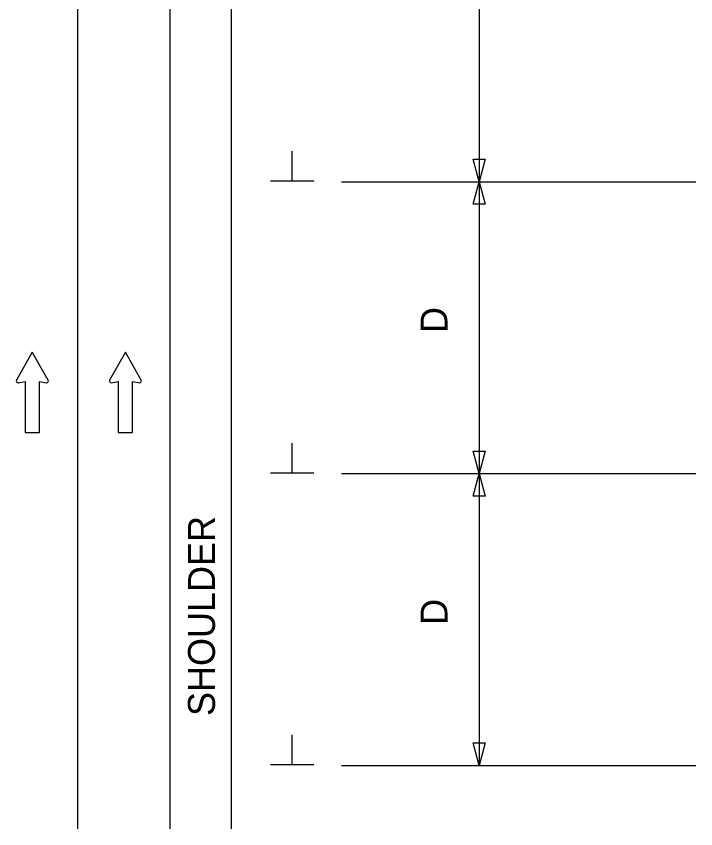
# Model space of a CAD drawing. Extents: x 19023 to 20762, y 4888 to 6104.
# Drawn here: x 19347 to 19523.7, y 5261 to 5472.4 of the extents above; entities that cross this region are included whole.
import ezdxf

# ---------------------------------------------------------------- set-up
doc = ezdxf.new("R2010")
doc.units = 0
for name, color, linetype in [('MT_SCRATCH_LEVEL_E', 7, 'Continuous'), ('PAVT_EDGE_EX', 7, 'Continuous'), ('TYPICAL_TEXT_DIMEN_PR', 7, 'Continuous')]:
    doc.layers.add(name, color=color, linetype=linetype)

msp = doc.modelspace()

# ---------------------------------------------------------------- linework, layer by layer
at = {"layer": 'MT_SCRATCH_LEVEL_E'}
for p, q in [((19351.148, 5384.986), (19347.037, 5377.745)), ((19351.148, 5384.986), (19347.037, 5377.745)), ((19355.295, 5377.745), (19351.148, 5384.986)), ((19355.295, 5377.745), (19351.148, 5384.986)), ((19375.362, 5384.986), (19371.251, 5377.745)), ((19375.362, 5384.986), (19371.251, 5377.745)), ((19379.509, 5377.745), (19375.362, 5384.986)), ((19379.509, 5377.745), (19375.362, 5384.986)), ((19347.519, 5377.061), (19349.296, 5377.377)), ((19347.519, 5377.061), (19349.296, 5377.377)), ((19349.296, 5377.377), (19349.296, 5364.119)), ((19349.296, 5377.377), (19349.296, 5364.119)), ((19353.038, 5364.119), (19353.038, 5377.377)), ((19353.038, 5377.377), (19354.816, 5377.061)), ((19353.038, 5364.119), (19353.038, 5377.377)), ((19353.038, 5377.377), (19354.816, 5377.061)), ((19371.733, 5377.061), (19373.51, 5377.377)), ((19371.733, 5377.061), (19373.51, 5377.377)), ((19373.51, 5377.377), (19373.51, 5364.119)), ((19373.51, 5377.377), (19373.51, 5364.119)), ((19377.252, 5364.119), (19377.252, 5377.377)), ((19377.252, 5377.377), (19379.03, 5377.061)), ((19377.252, 5364.119), (19377.252, 5377.377)), ((19377.252, 5377.377), (19379.03, 5377.061)), ((19349.296, 5364.119), (19353.038, 5364.119)), ((19349.296, 5364.119), (19353.038, 5364.119)), ((19373.51, 5364.119), (19377.252, 5364.119)), ((19373.51, 5364.119), (19377.252, 5364.119))]:
    msp.add_line(p, q, dxfattribs=at)
for centre, start, end in [((19347.445, 5377.521), 150.42484, 279.96381), ((19347.445, 5377.521), 150.42484, 279.96381), ((19354.885, 5377.522), 260.03619, 29.77312), ((19354.885, 5377.522), 260.03619, 29.77312), ((19371.659, 5377.521), 150.42484, 279.96381), ((19371.659, 5377.521), 150.42484, 279.96381), ((19379.099, 5377.522), 260.03619, 29.77312), ((19379.099, 5377.522), 260.03619, 29.77312)]:
    msp.add_arc(centre, 0.463, start, end, dxfattribs=at)
at = {"layer": 'PAVT_EDGE_EX'}
for p, q in [((19386.917, 6104.026), (19386.917, 5261.047)), ((19402.917, 6104.026), (19402.917, 5261.047)), ((19362.917, 6014.455), (19362.917, 5261.047))]:
    msp.add_line(p, q, dxfattribs=at)
for points in [[(19362.917, 5414.455), (19362.917, 5389.455)], [(19362.917, 5314.455), (19362.917, 5289.455)]]:
    msp.add_lwpolyline(points, dxfattribs=at)
at = {"layer": 'TYPICAL_TEXT_DIMEN_PR'}
for p, q in [((19467.405, 5581.162), (19467.405, 5277.497)), ((19418.735, 5429.493), (19418.735, 5437.278)), ((19418.761, 5429.493), (19418.761, 5437.278)), ((19418.761, 5429.493), (19418.761, 5437.278)), ((19467.389, 5429.339), (19465.818, 5435.201)), ((19465.818, 5435.201), (19467.389, 5435.201)), ((19467.389, 5435.201), (19468.96, 5435.201)), ((19468.96, 5435.201), (19467.389, 5429.339)), ((19418.735, 5429.493), (19413.11, 5429.493)), ((19418.761, 5429.493), (19413.136, 5429.493)), ((19418.761, 5429.493), (19413.136, 5429.493)), ((19424.36, 5429.493), (19418.735, 5429.493)), ((19424.386, 5429.493), (19418.761, 5429.493)), ((19424.386, 5429.493), (19418.761, 5429.493)), ((19431.588, 5429.331), (19523.722, 5429.331)), ((19465.815, 5423.484), (19467.386, 5429.346)), ((19467.386, 5429.346), (19468.957, 5423.484)), ((19467.386, 5423.484), (19465.815, 5423.484)), ((19468.957, 5423.484), (19467.386, 5423.484)), ((19418.761, 5353.576), (19418.761, 5361.361)), ((19467.389, 5353.422), (19465.818, 5359.284)), ((19465.818, 5359.284), (19467.389, 5359.284)), ((19467.389, 5359.284), (19468.96, 5359.284)), ((19468.96, 5359.284), (19467.389, 5353.422)), ((19418.761, 5353.576), (19413.136, 5353.576)), ((19424.386, 5353.576), (19418.761, 5353.576)), ((19431.588, 5353.414), (19523.722, 5353.414)), ((19465.815, 5347.567), (19467.386, 5353.429)), ((19467.386, 5353.429), (19468.957, 5347.567)), ((19467.386, 5347.567), (19465.815, 5347.567)), ((19468.957, 5347.567), (19467.386, 5347.567)), ((19418.761, 5277.659), (19418.761, 5285.444)), ((19467.389, 5277.505), (19465.818, 5283.367)), ((19465.818, 5283.367), (19467.389, 5283.367)), ((19467.389, 5283.367), (19468.96, 5283.367)), ((19468.96, 5283.367), (19467.389, 5277.505)), ((19418.761, 5277.659), (19413.136, 5277.659)), ((19424.386, 5277.659), (19418.761, 5277.659)), ((19431.588, 5277.497), (19523.722, 5277.497)), ((19431.588, 5277.497), (19523.722, 5277.497))]:
    msp.add_line(p, q, dxfattribs=at)

# ---------------------------------------------------------------- texts
for s, p in [('D', (19459.152, 5389.993)), ('SHOULDER', (19398.66, 5290.377)), ('D', (19459.152, 5314.076))]:
    msp.add_text(s, height=7, rotation=90, dxfattribs=at).set_placement(p)

doc.saveas('drawing.dxf')
